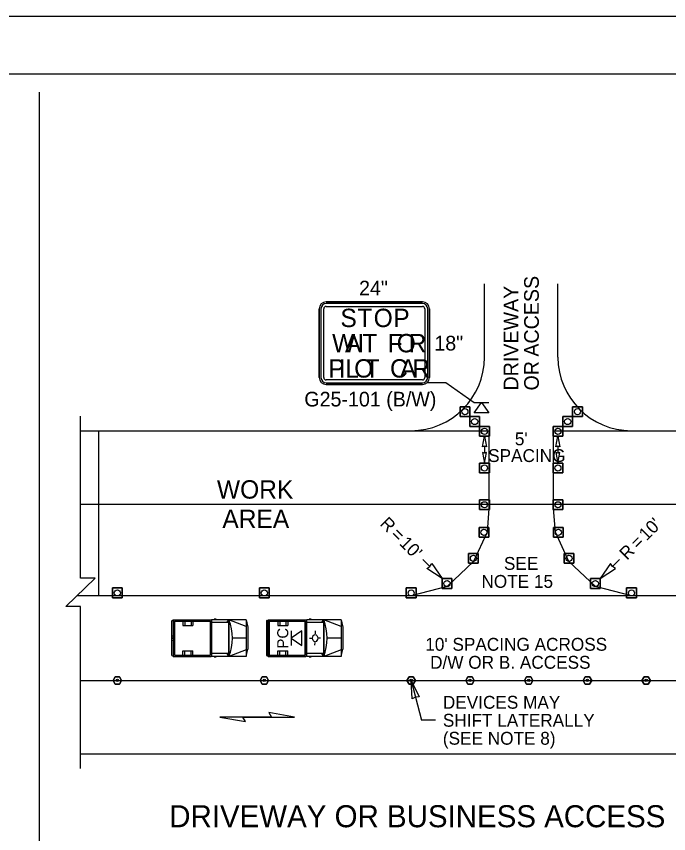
# Model space of a CAD drawing. Extents: x 99998.9 to 100095.7, y 99995 to 100010.7.
# Drawn here: x 100070.375 to 100073.928, y 100006.235 to 100010.687 of the extents above; entities that cross this region are included whole.
import ezdxf

# ---------------------------------------------------------------- set-up
doc = ezdxf.new("R2010")
doc.units = 0
for name, color, linetype in [('RD_ED_DrivewayEdge', 7, 'Continuous'), ('RD_ED_ShoulderPavedEdge', 7, 'Continuous'), ('RD_MK_LineEdgeWhite', 7, 'Continuous'), ('RD_MK_LineSkipCenter', 7, 'Continuous'), ('SH_DE_DetailHeading2Text', 7, 'Continuous'), ('SH_GI_PlotLimits', 7, 'Continuous'), ('SH_GI_SheetBorder', 7, 'Continuous'), ('TR_SN_ConstructionSigns', 7, 'Continuous'), ('TR_WZ_MotoristVehicle', 7, 'Continuous'), ('TR_WZ_PortableSignMountBlk-Wht', 7, 'Continuous'), ('TR_WZ_TrafficCone', 7, 'Continuous'), ('TR_WZ_TubularMarker', 7, 'Continuous'), ('TR_WZ_WorkAreaLabel', 7, 'Continuous'), ('TR_WZ_WorkZoneDetails', 7, 'Continuous'), ('TR_WZ_WorkZoneTextCurrent', 7, 'Continuous')]:
    doc.layers.add(name, color=color, linetype=linetype)

msp = doc.modelspace()

# ---------------------------------------------------------------- linework, layer by layer
at = {"layer": 'RD_ED_DrivewayEdge'}
for p, q in [((100072.925, 100008.8304), (100072.925, 100009.2305)), ((100073.325, 100008.8304), (100073.325, 100009.2305))]:
    msp.add_line(p, q, dxfattribs=at)
for centre, start, end in [((100072.525, 100008.8304), 270, 0), ((100073.725, 100008.8304), 180, 270)]:
    msp.add_arc(centre, 0.4, start, end, dxfattribs=at)
at = {"layer": 'RD_ED_ShoulderPavedEdge'}
for p, q in [((100070.725, 100008.4305), (100072.525, 100008.4305)), ((100073.725, 100008.4305), (100075.525, 100008.4305)), ((100070.725, 100006.6704), (100075.525, 100006.6704))]:
    msp.add_line(p, q, dxfattribs=at)
at = {"layer": 'RD_MK_LineEdgeWhite'}
for p, q in [((100070.725, 100008.0305), (100075.525, 100008.0305)), ((100070.725, 100007.0704), (100075.525, 100007.0704))]:
    msp.add_line(p, q, dxfattribs=at)
at = {"layer": 'RD_MK_LineSkipCenter'}
msp.add_lwpolyline([(100075.5043, 100007.5305), (100070.7043, 100007.5305)], dxfattribs=at)
at = {"layer": 'SH_GI_PlotLimits'}
msp.add_lwpolyline([(100059.0625, 99999.6875), (100076.0625, 99999.6875), (100076.0625, 100010.6875), (100059.0625, 100010.6875)], close=True, dxfattribs=at)
at = {"layer": 'SH_GI_SheetBorder'}
msp.add_line((100060, 100010.375), (100075.75, 100010.375), dxfattribs=at)
at = {"layer": 'TR_SN_ConstructionSigns'}
for p, q in [((100072.025, 100008.7198), (100072.025, 100009.0948)), ((100072.025, 100009.0948), (100072.025, 100008.7198)), ((100072.025, 100009.0948), (100072.025, 100008.7198)), ((100072.0344, 100009.0948), (100072.0344, 100008.7198)), ((100072.05, 100008.7198), (100072.05, 100009.0948)), ((100072.0625, 100009.1323), (100072.5875, 100009.1323)), ((100072.5875, 100009.1323), (100072.0625, 100009.1323)), ((100072.5875, 100009.1323), (100072.0625, 100009.1323)), ((100072.5875, 100009.1229), (100072.0625, 100009.1229)), ((100072.0625, 100009.1073), (100072.5875, 100009.1073)), ((100072.6, 100009.0948), (100072.6, 100008.7198)), ((100072.6156, 100008.7198), (100072.6156, 100009.0948)), ((100072.625, 100009.0948), (100072.625, 100008.7198)), ((100072.625, 100008.7198), (100072.625, 100009.0948)), ((100072.625, 100008.7198), (100072.625, 100009.0948)), ((100072.5875, 100008.7073), (100072.0625, 100008.7073)), ((100072.0625, 100008.6916), (100072.5875, 100008.6916)), ((100072.5875, 100008.6823), (100072.0625, 100008.6823)), ((100072.0625, 100008.6823), (100072.5875, 100008.6823)), ((100072.0625, 100008.6823), (100072.5875, 100008.6823))]:
    msp.add_line(p, q, dxfattribs=at)
for centre, radius, start, end in [((100072.0625, 100009.0948), 0.0375, 90, 180), ((100072.0625, 100009.0948), 0.0375, 90, 180), ((100072.0625, 100009.0948), 0.0375, 90, 180), ((100072.0625, 100009.0948), 0.0281, 90, 180), ((100072.0625, 100009.0948), 0.0125, 90, 180), ((100072.5875, 100009.0948), 0.0375, 0, 90), ((100072.5875, 100009.0948), 0.0375, 0, 90), ((100072.5875, 100009.0948), 0.0375, 0, 90), ((100072.5875, 100009.0948), 0.0281, 0, 90), ((100072.5875, 100009.0948), 0.0125, 0, 90), ((100072.0625, 100008.7198), 0.0375, 180, 270), ((100072.0625, 100008.7198), 0.0375, 180, 270), ((100072.0625, 100008.7198), 0.0375, 180, 270), ((100072.0625, 100008.7198), 0.0281, 180, 270), ((100072.0625, 100008.7198), 0.0125, 180, 270), ((100072.5875, 100008.7198), 0.0375, 270, 0), ((100072.5875, 100008.7198), 0.0375, 270, 0), ((100072.5875, 100008.7198), 0.0281, 270, 0), ((100072.5875, 100008.7198), 0.0125, 270, 0), ((100072.5875, 100008.7198), 0.0375, 270, 0)]:
    msp.add_arc(centre, radius, start, end, dxfattribs=at)
at = {"layer": 'TR_WZ_MotoristVehicle'}
for p, q in [((100071.4646, 100007.4033), (100071.4533, 100007.4033)), ((100071.9809, 100007.4033), (100071.9695, 100007.4033)), ((100071.2207, 100007.3911), (100071.2207, 100007.2098)), ((100071.2252, 100007.3972), (100071.2297, 100007.3972)), ((100071.2297, 100007.3972), (100071.2297, 100007.2037)), ((100071.2304, 100007.4005), (100071.4361, 100007.4005)), ((100071.2304, 100007.4005), (100071.2304, 100007.2005)), ((100071.2362, 100007.3925), (100071.2362, 100007.2084)), ((100071.2362, 100007.3925), (100071.4302, 100007.3925)), ((100071.2826, 100007.3925), (100071.2826, 100007.3695)), ((100071.2826, 100007.3695), (100071.3375, 100007.3695)), ((100071.2936, 100007.3925), (100071.2936, 100007.3695)), ((100071.3276, 100007.3925), (100071.3276, 100007.3695)), ((100071.3375, 100007.3925), (100071.3375, 100007.3695)), ((100071.4302, 100007.3925), (100071.4302, 100007.2084)), ((100071.4361, 100007.4005), (100071.4361, 100007.2005)), ((100071.4388, 100007.4005), (100071.4388, 100007.2005)), ((100071.6277, 100007.4005), (100071.4388, 100007.4005)), ((100071.5316, 100007.385), (100071.4388, 100007.385)), ((100071.5316, 100007.4005), (100071.5195, 100007.385)), ((100071.5316, 100007.4005), (100071.5316, 100007.2005)), ((100071.5333, 100007.4005), (100071.5333, 100007.2005)), ((100071.6277, 100007.3638), (100071.5333, 100007.4005)), ((100071.6277, 100007.4005), (100071.6277, 100007.2005)), ((100071.6277, 100007.4005), (100071.637, 100007.3601)), ((100071.637, 100007.3601), (100071.637, 100007.2408)), ((100071.737, 100007.3911), (100071.737, 100007.2098)), ((100071.7415, 100007.3972), (100071.7459, 100007.3972)), ((100071.7459, 100007.3972), (100071.7459, 100007.2037)), ((100071.7466, 100007.4005), (100071.9523, 100007.4005)), ((100071.7466, 100007.4005), (100071.7466, 100007.2005)), ((100071.7525, 100007.3925), (100071.7525, 100007.2084)), ((100071.7525, 100007.3925), (100071.9465, 100007.3925)), ((100071.7988, 100007.3925), (100071.7988, 100007.3695)), ((100071.7988, 100007.3695), (100071.8538, 100007.3695)), ((100071.8098, 100007.3925), (100071.8098, 100007.3695)), ((100071.8438, 100007.3925), (100071.8438, 100007.3695)), ((100071.8538, 100007.3925), (100071.8538, 100007.3695)), ((100071.9465, 100007.3925), (100071.9465, 100007.2084)), ((100071.9523, 100007.4005), (100071.9523, 100007.2005)), ((100071.9551, 100007.4005), (100071.9551, 100007.2005)), ((100072.144, 100007.4005), (100071.9551, 100007.4005)), ((100072.0478, 100007.385), (100071.9551, 100007.385)), ((100072.0478, 100007.4005), (100072.0358, 100007.385)), ((100072.0478, 100007.4005), (100072.0478, 100007.2005)), ((100072.0495, 100007.4005), (100072.0495, 100007.2005)), ((100072.144, 100007.3638), (100072.0495, 100007.4005)), ((100072.144, 100007.4005), (100072.144, 100007.2005)), ((100072.144, 100007.4005), (100072.1533, 100007.3601)), ((100072.1533, 100007.3601), (100072.1533, 100007.2408)), ((100071.2207, 100007.3145), (100071.2297, 100007.3108)), ((100071.737, 100007.3145), (100071.7459, 100007.3108)), ((100072.0025, 100007.3401), (100072.0025, 100007.3239)), ((100071.2207, 100007.2864), (100071.2297, 100007.2901)), ((100071.2231, 100007.3005), (100071.2273, 100007.3005)), ((100071.2252, 100007.3033), (100071.2252, 100007.2976)), ((100071.6277, 100007.3005), (100071.5518, 100007.3005)), ((100071.737, 100007.2864), (100071.7459, 100007.2901)), ((100071.7394, 100007.3005), (100071.7435, 100007.3005)), ((100071.7415, 100007.3033), (100071.7415, 100007.2976)), ((100071.9716, 100007.2997), (100071.9865, 100007.3001)), ((100071.9884, 100007.3001), (100071.9884, 100007.3001)), ((100072.0018, 100007.262), (100072.0021, 100007.277)), ((100072.0326, 100007.3006), (100072.02, 100007.3005)), ((100072.144, 100007.3005), (100072.0681, 100007.3005)), ((100071.2826, 100007.2084), (100071.2826, 100007.2314)), ((100071.2826, 100007.2314), (100071.3375, 100007.2314)), ((100071.2936, 100007.2084), (100071.2936, 100007.2314)), ((100071.3276, 100007.2084), (100071.3276, 100007.2314)), ((100071.3375, 100007.2084), (100071.3375, 100007.2314)), ((100071.6277, 100007.2371), (100071.5333, 100007.2005)), ((100071.6277, 100007.2005), (100071.637, 100007.2408)), ((100071.7988, 100007.2084), (100071.7988, 100007.2314)), ((100071.7988, 100007.2314), (100071.8538, 100007.2314)), ((100071.8098, 100007.2084), (100071.8098, 100007.2314)), ((100071.8438, 100007.2084), (100071.8438, 100007.2314)), ((100071.8538, 100007.2084), (100071.8538, 100007.2314)), ((100072.144, 100007.2371), (100072.0495, 100007.2005)), ((100072.144, 100007.2005), (100072.1533, 100007.2408)), ((100071.2252, 100007.2037), (100071.2297, 100007.2037)), ((100071.2304, 100007.2005), (100071.4361, 100007.2005)), ((100071.2362, 100007.2084), (100071.4302, 100007.2084)), ((100071.5316, 100007.216), (100071.4388, 100007.216)), ((100071.6277, 100007.2005), (100071.4388, 100007.2005)), ((100071.4646, 100007.1976), (100071.4533, 100007.1976)), ((100071.5216, 100007.216), (100071.5316, 100007.2005)), ((100071.7415, 100007.2037), (100071.7459, 100007.2037)), ((100071.7466, 100007.2005), (100071.9523, 100007.2005)), ((100071.7525, 100007.2084), (100071.9465, 100007.2084)), ((100072.0478, 100007.216), (100071.9551, 100007.216)), ((100072.144, 100007.2005), (100071.9551, 100007.2005)), ((100071.9809, 100007.1976), (100071.9695, 100007.1976)), ((100072.0379, 100007.216), (100072.0478, 100007.2005))]:
    msp.add_line(p, q, dxfattribs=at)
for centre, major_axis, start_param, end_param in [((100071.2252, 100007.3911), (0, 0.0061), 6.283185, 7.853982), ((100071.3983, 100007.3004), (0, 0.2099), 4.215852, 5.209111), ((100071.7415, 100007.3911), (0, 0.0061), 6.283185, 7.853982), ((100071.9146, 100007.3004), (0, 0.2099), 4.215852, 5.209111), ((100071.2252, 100007.2098), (0, -0.0061), 4.712389, 6.283185), ((100071.7415, 100007.2098), (0, -0.0061), 4.712389, 6.283185)]:
    msp.add_ellipse(centre, major_axis=major_axis, ratio=0.73155, start_param=start_param, end_param=end_param, dxfattribs=at)
for centre, major_axis in [((100072.0025, 100007.3005), (0, -0.0193)), ((100071.2252, 100007.3005), (0, -0.00282)), ((100071.7415, 100007.3005), (0, -0.00282))]:
    msp.add_ellipse(centre, major_axis=major_axis, ratio=0.73155, dxfattribs=at)
at = {"layer": 'TR_WZ_PortableSignMountBlk-Wht'}
for p, q in [((100072.8683, 100008.5846), (100072.9483, 100008.5846)), ((100071.8727, 100007.3404), (100071.8727, 100007.2604))]:
    msp.add_line(p, q, dxfattribs=at)
for points in [[(100072.9083, 100008.5846), (100072.9483, 100008.5271), (100072.8683, 100008.5271)], [(100071.8727, 100007.3004), (100071.9301, 100007.2604), (100071.9301, 100007.3404)]]:
    msp.add_lwpolyline(points, close=True, dxfattribs=at)
at = {"layer": 'TR_WZ_TrafficCone'}
for points in [[(100072.7917, 100008.5605), (100072.845, 100008.5605), (100072.845, 100008.5071), (100072.7917, 100008.5071), (100072.7917, 100008.5605)], [(100072.7917, 100008.5071), (100072.845, 100008.5071), (100072.845, 100008.5605), (100072.7917, 100008.5605), (100072.7917, 100008.5071)], [(100073.405, 100008.5605), (100073.4583, 100008.5605), (100073.4583, 100008.5071), (100073.405, 100008.5071), (100073.405, 100008.5605)], [(100073.405, 100008.5071), (100073.4583, 100008.5071), (100073.4583, 100008.5605), (100073.405, 100008.5605), (100073.405, 100008.5071)], [(100072.845, 100008.5071), (100072.8984, 100008.5071), (100072.8984, 100008.4538), (100072.845, 100008.4538), (100072.845, 100008.5071)], [(100072.845, 100008.4538), (100072.8984, 100008.4538), (100072.8984, 100008.5071), (100072.845, 100008.5071), (100072.845, 100008.4538)], [(100073.3516, 100008.5071), (100073.405, 100008.5071), (100073.405, 100008.4538), (100073.3516, 100008.4538), (100073.3516, 100008.5071)], [(100073.3516, 100008.4538), (100073.405, 100008.4538), (100073.405, 100008.5071), (100073.3516, 100008.5071), (100073.3516, 100008.4538)], [(100072.8984, 100008.4538), (100072.9517, 100008.4538), (100072.9517, 100008.4005), (100072.8984, 100008.4005), (100072.8984, 100008.4538)], [(100072.8984, 100008.4005), (100072.9517, 100008.4005), (100072.9517, 100008.4538), (100072.8984, 100008.4538), (100072.8984, 100008.4005)], [(100073.2983, 100008.4538), (100073.3516, 100008.4538), (100073.3516, 100008.4005), (100073.2983, 100008.4005), (100073.2983, 100008.4538)], [(100073.2983, 100008.4005), (100073.3516, 100008.4005), (100073.3516, 100008.4538), (100073.2983, 100008.4538), (100073.2983, 100008.4005)], [(100072.8984, 100008.2538), (100072.9517, 100008.2538), (100072.9517, 100008.2005), (100072.8984, 100008.2005), (100072.8984, 100008.2538)], [(100072.8984, 100008.2005), (100072.9517, 100008.2005), (100072.9517, 100008.2538), (100072.8984, 100008.2538), (100072.8984, 100008.2005)], [(100073.2983, 100008.2538), (100073.3516, 100008.2538), (100073.3516, 100008.2005), (100073.2983, 100008.2005), (100073.2983, 100008.2538)], [(100073.2983, 100008.2005), (100073.3516, 100008.2005), (100073.3516, 100008.2538), (100073.2983, 100008.2538), (100073.2983, 100008.2005)], [(100072.8984, 100008.0538), (100072.9517, 100008.0538), (100072.9517, 100008.0005), (100072.8984, 100008.0005), (100072.8984, 100008.0538)], [(100072.8984, 100008.0005), (100072.9517, 100008.0005), (100072.9517, 100008.0538), (100072.8984, 100008.0538), (100072.8984, 100008.0005)], [(100073.2983, 100008.0538), (100073.3516, 100008.0538), (100073.3516, 100008.0005), (100073.2983, 100008.0005), (100073.2983, 100008.0538)], [(100073.2983, 100008.0005), (100073.3516, 100008.0005), (100073.3516, 100008.0538), (100073.2983, 100008.0538), (100073.2983, 100008.0005)], [(100072.8956, 100007.9038), (100072.949, 100007.9038), (100072.949, 100007.8505), (100072.8956, 100007.8505), (100072.8956, 100007.9038)], [(100072.8956, 100007.8505), (100072.949, 100007.8505), (100072.949, 100007.9038), (100072.8956, 100007.9038), (100072.8956, 100007.8505)], [(100073.301, 100007.9038), (100073.3544, 100007.9038), (100073.3544, 100007.8505), (100073.301, 100007.8505), (100073.301, 100007.9038)], [(100073.301, 100007.8505), (100073.3544, 100007.8505), (100073.3544, 100007.9038), (100073.301, 100007.9038), (100073.301, 100007.8505)], [(100072.8381, 100007.7615), (100072.8914, 100007.7615), (100072.8914, 100007.7082), (100072.8381, 100007.7082), (100072.8381, 100007.7615)], [(100072.8381, 100007.7082), (100072.8914, 100007.7082), (100072.8914, 100007.7615), (100072.8381, 100007.7615), (100072.8381, 100007.7082)], [(100073.3586, 100007.7615), (100073.4119, 100007.7615), (100073.4119, 100007.7082), (100073.3586, 100007.7082), (100073.3586, 100007.7615)], [(100073.3586, 100007.7082), (100073.4119, 100007.7082), (100073.4119, 100007.7615), (100073.3586, 100007.7615), (100073.3586, 100007.7082)], [(100072.6944, 100007.6247), (100072.7477, 100007.6247), (100072.7477, 100007.5714), (100072.6944, 100007.5714), (100072.6944, 100007.6247)], [(100072.6944, 100007.5714), (100072.7477, 100007.5714), (100072.7477, 100007.6247), (100072.6944, 100007.6247), (100072.6944, 100007.5714)], [(100073.5023, 100007.6247), (100073.5556, 100007.6247), (100073.5556, 100007.5714), (100073.5023, 100007.5714), (100073.5023, 100007.6247)], [(100073.5023, 100007.5714), (100073.5556, 100007.5714), (100073.5556, 100007.6247), (100073.5023, 100007.6247), (100073.5023, 100007.5714)], [(100070.899, 100007.5738), (100070.9524, 100007.5738), (100070.9524, 100007.5205), (100070.899, 100007.5205), (100070.899, 100007.5738)], [(100070.899, 100007.5205), (100070.9524, 100007.5205), (100070.9524, 100007.5738), (100070.899, 100007.5738), (100070.899, 100007.5205)], [(100071.699, 100007.5738), (100071.7524, 100007.5738), (100071.7524, 100007.5205), (100071.699, 100007.5205), (100071.699, 100007.5738)], [(100071.699, 100007.5205), (100071.7524, 100007.5205), (100071.7524, 100007.5738), (100071.699, 100007.5738), (100071.699, 100007.5205)], [(100072.499, 100007.5738), (100072.5524, 100007.5738), (100072.5524, 100007.5205), (100072.499, 100007.5205), (100072.499, 100007.5738)], [(100072.499, 100007.5205), (100072.5524, 100007.5205), (100072.5524, 100007.5738), (100072.499, 100007.5738), (100072.499, 100007.5205)], [(100073.699, 100007.5738), (100073.7524, 100007.5738), (100073.7524, 100007.5205), (100073.699, 100007.5205), (100073.699, 100007.5738)], [(100073.699, 100007.5205), (100073.7524, 100007.5205), (100073.7524, 100007.5738), (100073.699, 100007.5738), (100073.699, 100007.5205)]]:
    msp.add_lwpolyline(points, dxfattribs=at)
for centre in [(100072.8184, 100008.5338), (100073.4316, 100008.5338), (100072.8717, 100008.4805), (100073.3783, 100008.4805), (100072.925, 100008.4271), (100073.325, 100008.4271), (100072.925, 100008.2271), (100073.325, 100008.2271), (100072.925, 100008.0271), (100073.325, 100008.0271), (100072.9223, 100007.8771), (100073.3277, 100007.8771), (100072.8648, 100007.7349), (100073.3852, 100007.7349), (100072.721, 100007.598), (100073.529, 100007.598), (100070.9257, 100007.5471), (100071.7257, 100007.5471), (100072.5257, 100007.5471), (100073.7257, 100007.5471)]:
    msp.add_circle(centre, 0.0167, dxfattribs=at)
at = {"layer": 'TR_WZ_TubularMarker'}
for points in [[(100070.9026, 100007.0704), (100070.9142, 100007.0904), (100070.9373, 100007.0904), (100070.9488, 100007.0704), (100070.9373, 100007.0504), (100070.9142, 100007.0504)], [(100071.7026, 100007.0704), (100071.7141, 100007.0904), (100071.7372, 100007.0904), (100071.7488, 100007.0704), (100071.7372, 100007.0504), (100071.7141, 100007.0504)], [(100072.5026, 100007.0704), (100072.5141, 100007.0904), (100072.5372, 100007.0904), (100072.5488, 100007.0704), (100072.5372, 100007.0504), (100072.5141, 100007.0504)], [(100072.8226, 100007.0704), (100072.8341, 100007.0904), (100072.8572, 100007.0904), (100072.8688, 100007.0704), (100072.8572, 100007.0504), (100072.8341, 100007.0504)], [(100073.1426, 100007.0704), (100073.1541, 100007.0904), (100073.1772, 100007.0904), (100073.1888, 100007.0704), (100073.1772, 100007.0504), (100073.1541, 100007.0504)], [(100073.4626, 100007.0704), (100073.4741, 100007.0904), (100073.4972, 100007.0904), (100073.5088, 100007.0704), (100073.4972, 100007.0504), (100073.4741, 100007.0504)], [(100073.7826, 100007.0704), (100073.7941, 100007.0904), (100073.8172, 100007.0904), (100073.8288, 100007.0704), (100073.8172, 100007.0504), (100073.7941, 100007.0504)]]:
    msp.add_lwpolyline(points, close=True, dxfattribs=at)
for points in [[(100070.9142, 100007.0504), (100070.9373, 100007.0504), (100070.9488, 100007.0704), (100070.9373, 100007.0904), (100070.9142, 100007.0904), (100070.9026, 100007.0704), (100070.9142, 100007.0504)], [(100071.7141, 100007.0504), (100071.7372, 100007.0504), (100071.7488, 100007.0704), (100071.7372, 100007.0904), (100071.7141, 100007.0904), (100071.7026, 100007.0704), (100071.7141, 100007.0504)], [(100072.5141, 100007.0504), (100072.5372, 100007.0504), (100072.5488, 100007.0704), (100072.5372, 100007.0904), (100072.5141, 100007.0904), (100072.5026, 100007.0704), (100072.5141, 100007.0504)], [(100072.8341, 100007.0504), (100072.8572, 100007.0504), (100072.8688, 100007.0704), (100072.8572, 100007.0904), (100072.8341, 100007.0904), (100072.8226, 100007.0704), (100072.8341, 100007.0504)], [(100073.1541, 100007.0504), (100073.1772, 100007.0504), (100073.1888, 100007.0704), (100073.1772, 100007.0904), (100073.1541, 100007.0904), (100073.1426, 100007.0704), (100073.1541, 100007.0504)], [(100073.4741, 100007.0504), (100073.4972, 100007.0504), (100073.5088, 100007.0704), (100073.4972, 100007.0904), (100073.4741, 100007.0904), (100073.4626, 100007.0704), (100073.4741, 100007.0504)], [(100073.7941, 100007.0504), (100073.8172, 100007.0504), (100073.8288, 100007.0704), (100073.8172, 100007.0904), (100073.7941, 100007.0904), (100073.7826, 100007.0704), (100073.7941, 100007.0504)]]:
    msp.add_lwpolyline(points, dxfattribs=at)
for centre in [(100070.9257, 100007.0704), (100071.7257, 100007.0704), (100072.5257, 100007.0704), (100072.8457, 100007.0704), (100073.1657, 100007.0704), (100073.4857, 100007.0704), (100073.8057, 100007.0704)]:
    msp.add_circle(centre, 0.00667, dxfattribs=at)
at = {"layer": 'TR_WZ_WorkZoneDetails'}
for p, q in [((100070.5, 100010.275), (100070.5, 100001.6859)), ((100072.614, 100008.6933), (100072.714, 100008.6933)), ((100072.714, 100008.6933), (100072.8683, 100008.5846)), ((100072.9251, 100008.3459), (100072.9251, 100008.3083)), ((100073.325, 100008.3459), (100073.325, 100008.3083)), ((100072.6281, 100007.691), (100072.5897, 100007.7294)), ((100073.6219, 100007.691), (100073.6603, 100007.7294)), ((100072.5257, 100007.0704), (100072.5821, 100006.853)), ((100071.7642, 100006.8704), (100071.6098, 100006.8704)), ((100071.6098, 100006.8704), (100071.7642, 100006.8704)), ((100072.6583, 100006.853), (100072.5821, 100006.853))]:
    msp.add_line(p, q, dxfattribs=at)
msp.add_lwpolyline([(100070.725, 100006.5904), (100070.725, 100007.473), (100070.645, 100007.473), (100070.805, 100007.6279), (100070.725, 100007.6279), (100070.725, 100008.5105)], dxfattribs=at)
for points in [[(100072.9483, 100008.4305), (100072.9483, 100008.2071), (100072.9483, 100008.0071), (100072.939, 100007.8771), (100072.939, 100007.8771), (100072.939, 100007.8771), (100072.8648, 100007.7182), (100072.8648, 100007.7182), (100072.8648, 100007.7182), (100072.721, 100007.5814), (100072.5257, 100007.5305), (100071.529, 100007.5305), (100070.949, 100007.5305), (100070.825, 100007.5305), (100070.825, 100008.4305)], [(100075.425, 100008.4305), (100075.425, 100008.0305), (100075.425, 100007.5305), (100074.501, 100007.5305), (100074.501, 100007.5305), (100074.501, 100007.5305), (100073.7257, 100007.5305), (100073.7257, 100007.5305), (100073.7257, 100007.5305), (100073.529, 100007.5814), (100073.3852, 100007.7182), (100073.311, 100007.8771), (100073.3017, 100008.0071), (100073.3017, 100008.2071), (100073.3017, 100008.4305)], [(100072.925, 100008.4005), (100072.9363, 100008.3433), (100072.925, 100008.3459), (100072.9138, 100008.3433)], [(100073.325, 100008.4005), (100073.3362, 100008.3433), (100073.325, 100008.3459), (100073.3137, 100008.3433)], [(100072.9251, 100008.2538), (100072.9363, 100008.3109), (100072.9251, 100008.3083), (100072.9139, 100008.3109)], [(100073.325, 100008.2538), (100073.3362, 100008.3109), (100073.325, 100008.3083), (100073.3138, 100008.3109)], [(100072.6944, 100007.6247), (100072.6113, 100007.6806), (100072.6281, 100007.691), (100072.6385, 100007.7079)], [(100073.5556, 100007.6247), (100073.6387, 100007.6806), (100073.6219, 100007.691), (100073.6115, 100007.7079)], [(100072.5257, 100007.0704), (100072.569, 100006.9801), (100072.5492, 100006.9797), (100072.5316, 100006.9705)], [(100071.4841, 100006.8704), (100071.6241, 100006.8458), (100071.6098, 100006.8704)], [(100071.8899, 100006.8704), (100071.7499, 100006.8951), (100071.7642, 100006.8704)]]:
    msp.add_lwpolyline(points, close=True, dxfattribs=at)

# ---------------------------------------------------------------- texts
at = {"layer": 'SH_DE_DetailHeading2Text'}
msp.add_text('DRIVEWAY OR BUSINESS ACCESS DETAIL', height=0.12, rotation=360, dxfattribs=at).set_placement((100071.2082, 100006.2704))
at = {"layer": 'TR_SN_ConstructionSigns'}
for s, p in [('24"', (100072.2419, 100009.1673)), ('18"', (100072.6519, 100008.8673)), ('G25-101 (B/W)', (100071.9438, 100008.5623))]:
    msp.add_text(s, height=0.08, rotation=360, dxfattribs=at).set_placement(p)
for s, p in [('S', (100072.1405, 100008.9948)), ('T', (100072.2325, 100008.9948)), ('O', (100072.3215, 100008.9948)), ('P', (100072.4285, 100008.9948)), ('W', (100072.095, 100008.8573)), ('A', (100072.165, 100008.8573)), ('I', (100072.233, 100008.8573)), ('T', (100072.26, 100008.8573)), ('F', (100072.398, 100008.8573)), ('O', (100072.447, 100008.8573)), ('R', (100072.512, 100008.8573)), ('P', (100072.0745, 100008.7198)), ('I', (100072.1315, 100008.7198)), ('L', (100072.1665, 100008.7198)), ('O', (100072.2155, 100008.7198)), ('T', (100072.2725, 100008.7198)), ('C', (100072.4105, 100008.7198)), ('A', (100072.4645, 100008.7198)), ('R', (100072.5325, 100008.7198))]:
    msp.add_text(s, height=0.1, dxfattribs=at).set_placement(p)
at = {"layer": 'TR_WZ_MotoristVehicle'}
msp.add_text('PC', height=0.06, rotation=90, dxfattribs=at).set_placement((100071.8563, 100007.2444))
at = {"layer": 'TR_WZ_WorkAreaLabel'}
for s, p in [('WORK', (100071.4678, 100008.0605)), ('AREA', (100071.4974, 100007.9004))]:
    msp.add_text(s, height=0.1, dxfattribs=at).set_placement(p)
at = {"layer": 'TR_WZ_WorkZoneTextCurrent'}
for s, height, rotation, p in [('ACCESS', 0.08, 90, (100073.221, 100008.8338)), ('DRIVEWAY', 0.08, 90, (100073.109, 100008.6495)), ('OR', 0.08, 90, (100073.221, 100008.6495)), ('R', 0.07, 315, (100072.3509, 100007.9186)), ("10'", 0.07, 45, (100073.8075, 100007.8271)), ('=', 0.07, 315, (100072.4101, 100007.8595)), ("10'", 0.07, 315, (100072.457, 100007.8126)), ('=', 0.07, 45, (100073.7606, 100007.7802)), ('R', 0.07, 45, (100073.7015, 100007.7211))]:
    msp.add_text(s, height=height, rotation=rotation, dxfattribs=at).set_placement(p)
for s, p in [("5'", (100073.0904, 100008.3509)), ('SPACING', (100072.945, 100008.2599)), ('SEE', (100073.0308, 100007.6725)), ('NOTE 15', (100072.9084, 100007.5745)), ("10' SPACING ACROSS", (100072.6026, 100007.2318)), ('D/W OR B. ACCESS', (100072.6288, 100007.1338)), ('DEVICES MAY', (100072.6983, 100006.916)), ('SHIFT LATERALLY', (100072.6983, 100006.818)), ('(SEE NOTE 8)', (100072.6983, 100006.72))]:
    msp.add_text(s, height=0.07, dxfattribs=at).set_placement(p)

doc.saveas('drawing.dxf')
